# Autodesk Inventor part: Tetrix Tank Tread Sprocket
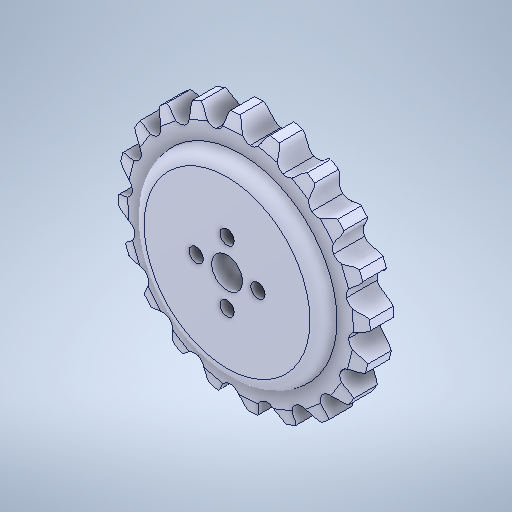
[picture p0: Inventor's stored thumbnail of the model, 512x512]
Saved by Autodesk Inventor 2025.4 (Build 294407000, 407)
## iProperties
Created: 2021-10
Part Number: Tetrix Tank Tread Sprocket
Material: Genérico
Document SubType Name: Modeling
Designer: usuario
Density: 1 g/cm^3
Appearance: Valor por defecto
Author: usuario
Sending System: SolidWorks 2016
Last Author: LENOVO
Last Saved: 2021-10-21
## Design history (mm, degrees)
chamfer "Chamfer2"
node "Plane1"
node "Sólido1"
